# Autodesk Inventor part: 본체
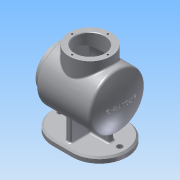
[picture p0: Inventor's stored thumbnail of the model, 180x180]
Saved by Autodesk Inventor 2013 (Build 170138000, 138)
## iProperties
Created: 2016-04
Part Number: 본체
Material: 알루미늄 6061
Document SubType Name: Modeling
Designer: Administrator
Density: 2.71 g/cm^3
Mass: 934.578 g
Surface Area: 1234.74 cm^2
Volume: 344.863 cm^3
Author: Administrator
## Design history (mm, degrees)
sketch "스케치1"
  geometry: L1 (-17.5, 50)-(17.5, 50); L2 (17.5, -50)-(-17.5, -50); A1 r 50 centre (17.5, 0) between (17.5, -50) and (17.5, 50); A2 r 50 centre (-17.5, 0) between (-17.5, 50) and (-17.5, -50); 2 further points
  constraints: 4 end point, 4 point on circle, 4 tangent, 2 centre point, 1 horizontal, 1 horizontal alignment, 1 midpoint, 1 parallel, 1 vertical alignment
  dimensions: "d0" = 135 dimension on A1 A2; "d2" = 100 distance between parallel lines of L2 L1
extrude "돌출1" new body sketch "스케치1" distance "d3" = 10; taper "d4" = 0 deg
sketch "스케치3"
  geometry: L1 (-46, 126)-(47.104, 126); L2 (-49, 129)-(49, 129); L3 (-61, 79)-(61, 79); L4 (-46, 101.5)-(-46, 126); L5 (-49, 117)-(-49, 129); L6 (-61, 101.5)-(-46, 101.5); L7 (-61, 101.5)-(-61, 117); L8 (-61, 117)-(-49, 117); L9 (17.5, 0)-(-17.5, 0) reference; A1 r 117 centre (-58.977, 76.646) between (57.999, 79) and (47.104, 126); A2 r 120 centre (-58.977, 76.646) between (61, 79) and (49, 129); 3 further points
  constraints: 17 end point, 4 point on circle, 3 parallel, 2 centre point, 2 horizontal, 2 midpoint, 2 perpendicular, 2 vertical alignment, 1 point on line, 1 vertical
  dimensions: "d17" = 122 distance of L3.end L3.start; "d18" = 45 diameter of L6 L3; "d19" = 76 diameter of L8 L3; "d20" = 94 diameter of L1 L3; "d21" = 100 diameter of L2 L3; "d22" = 12 distance of L7.end L5.start; "d23" = 120 radius of A2; "d24" = 12 horizontal distance of L3.end L2.end; "d25" = 3 distance between parallel lines of L4 L5; "d26" = 3 radial gap between concentric circles of A2 A1; "d27" = 79 distance from line of L9 point (0, 79)
revolve "회전1" sketch "스케치3" stored, may be unused: angle "d28" = 90 deg
sketch "스케치5"
  geometry: L1 (-17.5, 10)-(-67.5, 10) reference; L2 (67.5, 10)-(17.5, 10) reference; L3 (-49, 29)-(49, 29) reference; L4 (-40, 10)-(-36.25, 31.267); L5 (-36.25, 31.267)-(36.25, 31.267); L6 (36.25, 31.267)-(40, 10); 2 further points
  constraints: 6 end point, 2 point on line, 1 equal length, 1 midpoint, 1 parallel, 1 vertical alignment
  dimensions: "d37" = 40 horizontal distance of point (0, 0) L4.start; "d38" = 100 deg angle of L4 L1; "d39" = 72.5 distance of L4.end L5.end
feature "리브1" sketch "스케치5" dims "d40" = 1, "d41" = 10, "d42" = 0, "d43" = 0, "d44" = 1, "d45" = 1
node "작업 평면1"
sketch "스케치8"
  geometry: L1 (-40, 51.43)-(-40, 10); L2 (40, 51.43)-(40, 10); L3 (50, 10)-(-50, 10) reference; A1 r 49 centre (0, 79.732) between (-40, 51.43) and (40, 51.43); 1 further point
  constraints: 4 end point, 2 horizontal alignment, 2 point on circle, 2 point on line, 1 centre point, 1 parallel, 1 vertical
  dimensions: "d61" = 80 distance between parallel lines of L2 L1; "d68" = 49 radius of A1; "d69" = 40 horizontal distance of L1.end point (0, 0); "d70" = 79.73167 distance of A1.centre point (0, 0)
feature "리브2" sketch "스케치8" dims "d62" = 1, "d63" = 10, "d64" = 0, "d65" = 0, "d66" = 1, "d67" = 1
sketch "스케치9"
  geometry: 3 further points
  constraints: 2 horizontal alignment
  dimensions: "d71" = 54 distance of point (0, 0) point (-54, 0); "d72" = 54 distance of point (54, 0) point (0, 0)
hole "구멍1" sketch "스케치9" at (-54, 0), (54, 0) diameter "d73" = 10; stored, may be unused: countersink angle "d77" = 90 deg, drill point angle "d79" = 118 deg; dims "d74" = 6, "d75" = 4, "d76" = 2, "d78" = 8
node "작업 평면2"
sketch "스케치10"
  geometry: C1 r 38 at (0, 0); 1 further point
  constraints: 1 centre point, 1 coincident
  dimensions: "d81" = 76 diameter of C1
extrude "돌출4" join sketch "스케치10" distance "d83" = 38; taper "d84" = 0 deg
sketch "스케치11"
  geometry: C1 r 47 at (0, 79) reference; 1 further point
feature "돌출 곡면2" sketch "스케치11" dims "d85" = 78, "d86" = 0
feature "분할1"
hole "구멍2" diameter "d89" = 54; stored, may be unused: countersink angle "d93" = 90 deg, drill point angle "d95" = 118 deg; dims "d87" = 10, "d88" = 10, "d90" = 6, "d91" = 4, "d92" = 2, "d94" = 40
sketch "스케치12"
  geometry: A1 r 32.5 centre (0, 0) between (-32.5, 0) and (0, -32.5); 3 further points
  constraints: 4 point on circle, 3 horizontal alignment, 2 vertical alignment, 1 centre point
  dimensions: "d96" = 79 distance of point (79, 0) A1.centre; "d97" = 65 diameter of A1
hole "구멍3" sketch "스케치12" at (-32.5, 0), (0, -32.5), (0, 32.5), (32.5, 0) diameter "d98" = 3.242; stored, may be unused: countersink angle "d102" = 90 deg, drill point angle "d104" = 118 deg; dims "d99" = 8, "d100" = 4, "d101" = 2, "d103" = 10
sketch "스케치13"
  geometry: A1 r 32.5 centre (0, 0) between (0, 32.5) and (-32.5, 0); 3 further points
  constraints: 4 point on circle, 2 horizontal alignment, 2 vertical alignment, 1 centre point, 1 coincident
  dimensions: "d105" = 65 diameter of A1
hole "구멍4" sketch "스케치13" at (0, 32.5), (-32.5, 0), (0, -32.5), (32.5, 0) diameter "d107" = 3.242; stored, may be unused: countersink angle "d111" = 90 deg, drill point angle "d113" = 118 deg; dims "d108" = 8, "d109" = 4, "d110" = 2, "d112" = 10
node "작업 평면3"
node "작업 평면4"
sketch "스케치14"
  geometry: 2 further points
  constraints: 1 vertical alignment, 1 other
  dimensions: "d116" = 79 distance of point (0, 0) point (0, 79)
feature "엠보싱1" sketch "스케치14" dims "d0" = 135, "d2" = 100, "d117" = 0.5, "d118" = 0
chamfer "모따기1" distance "d119" = 3; stored, may be unused: second distance "d120" = 2, angle "d121" = 45 deg
chamfer "모따기2" distance "d122" = 1; stored, may be unused: second distance "d123" = 2, angle "d124" = 45 deg
fillet "모깎기1" dims "d125" = 5
fillet "모깎기2" dims "d126" = 2
fillet "모깎기3" dims "d127" = 3
fillet "모깎기4" dims "d128" = 3
node "솔리드1"
node "곡면2"
other parameters: "d46" = 144, "d80" = 144, "d114" = -48, "d115" = -61
